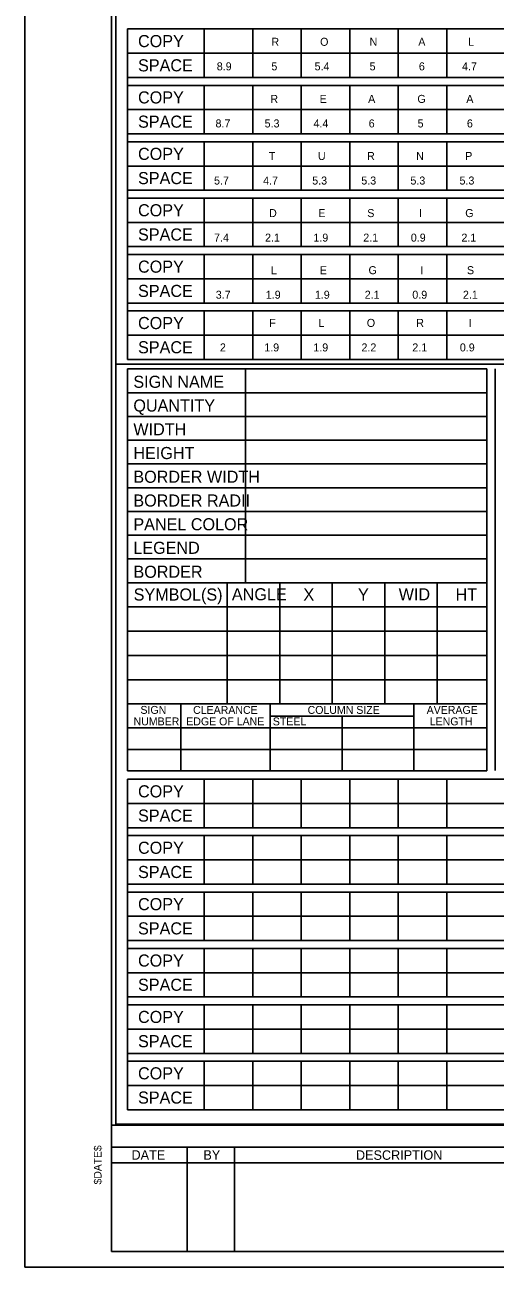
# Model space of a CAD drawing. Extents: x 17890628 to 17890844, y 17897693 to 17898031.
# Drawn here: x 17890700.5 to 17890726.4, y 17897907.6 to 17897976.1 of the extents above; entities that cross this region are included whole.
import ezdxf

# ---------------------------------------------------------------- set-up
doc = ezdxf.new("R2010")
doc.units = 0
for name, color, linetype in [('GSSign', 7, 'Continuous'), ('PlotBorder_dp', 7, 'Continuous'), ('SheetBorder_dp', 7, 'Continuous'), ('SheetLines_dp', 7, 'Continuous'), ('SheetLinesMisc2_dp', 7, 'Continuous'), ('TextMinor', 7, 'Continuous'), ('TextMisc', 7, 'Continuous')]:
    doc.layers.add(name, color=color, linetype=linetype)

msp = doc.modelspace()

# ---------------------------------------------------------------- linework, layer by layer
at = {"layer": 'PlotBorder_dp'}
msp.add_lwpolyline([(17890700.471, 17897907.61), (17890843.989, 17897907.61), (17890843.989, 17897999.809), (17890700.471, 17897999.809)], close=True, dxfattribs=at)
at = {"layer": 'SheetBorder_dp'}
for p, q in [((17890705.254, 17897998.94), (17890705.254, 17897908.479)), ((17890705.254, 17897915.438), (17890839.205, 17897915.438)), ((17890705.254, 17897908.479), (17890839.205, 17897908.479))]:
    msp.add_line(p, q, dxfattribs=at)
at = {"layer": 'SheetLines_dp'}
for p, q in [((17890705.254, 17897914.22), (17890755.355, 17897914.22)), ((17890709.43, 17897914.22), (17890709.43, 17897908.479)), ((17890712.039, 17897914.22), (17890712.039, 17897908.479)), ((17890705.254, 17897913.35), (17890755.355, 17897913.35))]:
    msp.add_line(p, q, dxfattribs=at)
at = {"layer": 'SheetLinesMisc2_dp'}
for p, q in [((17890705.5, 17897998.732), (17890705.5, 17897915.484)), ((17890706.142, 17897975.843), (17890771.912, 17897975.843)), ((17890706.142, 17897957.633), (17890706.142, 17897975.843)), ((17890710.375, 17897975.843), (17890710.375, 17897973.171)), ((17890713.051, 17897975.843), (17890713.051, 17897973.171)), ((17890715.727, 17897975.843), (17890715.727, 17897973.171)), ((17890718.402, 17897975.843), (17890718.402, 17897973.171)), ((17890721.077, 17897975.843), (17890721.077, 17897973.171)), ((17890723.753, 17897975.843), (17890723.753, 17897973.171)), ((17890706.142, 17897974.507), (17890771.912, 17897974.507)), ((17890706.142, 17897973.171), (17890771.912, 17897973.171)), ((17890706.142, 17897972.735), (17890771.912, 17897972.735)), ((17890710.375, 17897972.735), (17890710.375, 17897970.064)), ((17890713.051, 17897972.735), (17890713.051, 17897970.064)), ((17890715.727, 17897972.735), (17890715.727, 17897970.064)), ((17890718.402, 17897972.735), (17890718.402, 17897970.064)), ((17890721.077, 17897972.735), (17890721.077, 17897970.064)), ((17890723.753, 17897972.735), (17890723.753, 17897970.064)), ((17890706.142, 17897971.399), (17890771.912, 17897971.4)), ((17890706.142, 17897970.064), (17890771.912, 17897970.064)), ((17890706.142, 17897969.628), (17890771.912, 17897969.628)), ((17890710.375, 17897969.628), (17890710.375, 17897966.956)), ((17890713.051, 17897969.628), (17890713.051, 17897966.956)), ((17890715.727, 17897969.628), (17890715.727, 17897966.956)), ((17890718.402, 17897969.628), (17890718.402, 17897966.956)), ((17890721.077, 17897969.628), (17890721.077, 17897966.956)), ((17890723.753, 17897969.628), (17890723.753, 17897966.956)), ((17890706.142, 17897968.292), (17890771.912, 17897968.292)), ((17890706.142, 17897966.956), (17890771.912, 17897966.956)), ((17890706.142, 17897966.52), (17890771.912, 17897966.52)), ((17890710.375, 17897966.52), (17890710.375, 17897963.848)), ((17890713.051, 17897966.52), (17890713.051, 17897963.848)), ((17890715.727, 17897966.52), (17890715.727, 17897963.848)), ((17890718.402, 17897966.52), (17890718.402, 17897963.848)), ((17890721.077, 17897966.52), (17890721.077, 17897963.848)), ((17890723.753, 17897966.52), (17890723.753, 17897963.848)), ((17890706.142, 17897965.184), (17890771.912, 17897965.184)), ((17890706.142, 17897963.848), (17890771.912, 17897963.848)), ((17890706.142, 17897963.412), (17890771.912, 17897963.412)), ((17890710.375, 17897963.412), (17890710.375, 17897960.74)), ((17890713.051, 17897963.412), (17890713.051, 17897960.74)), ((17890715.727, 17897963.412), (17890715.727, 17897960.74)), ((17890718.402, 17897963.412), (17890718.402, 17897960.74)), ((17890721.077, 17897963.412), (17890721.077, 17897960.74)), ((17890723.753, 17897963.412), (17890723.753, 17897960.74)), ((17890706.142, 17897962.076), (17890771.912, 17897962.076)), ((17890706.142, 17897960.74), (17890771.912, 17897960.74)), ((17890706.142, 17897960.304), (17890771.912, 17897960.304)), ((17890710.375, 17897960.304), (17890710.375, 17897957.633)), ((17890713.051, 17897960.304), (17890713.051, 17897957.633)), ((17890715.727, 17897960.304), (17890715.727, 17897957.633)), ((17890718.402, 17897960.304), (17890718.402, 17897957.633)), ((17890721.077, 17897960.304), (17890721.077, 17897957.633)), ((17890723.753, 17897960.304), (17890723.753, 17897957.633)), ((17890706.142, 17897958.969), (17890771.912, 17897958.969)), ((17890705.5, 17897957.37), (17890839.233, 17897957.37)), ((17890706.142, 17897957.633), (17890771.912, 17897957.633)), ((17890706.142, 17897934.953), (17890706.142, 17897957.108)), ((17890706.142, 17897957.108), (17890725.973, 17897957.108)), ((17890712.643, 17897957.108), (17890712.643, 17897955.799)), ((17890725.973, 17897957.108), (17890725.973, 17897934.953)), ((17890726.429, 17897957.109), (17890726.429, 17897934.985)), ((17890706.142, 17897955.799), (17890725.973, 17897955.799)), ((17890712.643, 17897955.799), (17890712.643, 17897945.327)), ((17890706.142, 17897954.491), (17890725.973, 17897954.491)), ((17890706.142, 17897953.182), (17890725.973, 17897953.182)), ((17890706.142, 17897951.874), (17890725.973, 17897951.874)), ((17890706.142, 17897950.565), (17890725.973, 17897950.565)), ((17890706.142, 17897949.256), (17890725.973, 17897949.256)), ((17890706.142, 17897947.948), (17890716.057, 17897947.948)), ((17890716.057, 17897947.948), (17890725.973, 17897947.948)), ((17890706.142, 17897946.639), (17890716.057, 17897946.639)), ((17890716.057, 17897946.639), (17890725.973, 17897946.639)), ((17890706.141, 17897945.327), (17890725.973, 17897945.327)), ((17890711.644, 17897945.327), (17890711.644, 17897938.646)), ((17890714.542, 17897945.327), (17890714.542, 17897938.646)), ((17890717.44, 17897945.327), (17890717.44, 17897938.646)), ((17890720.337, 17897945.327), (17890720.337, 17897938.646)), ((17890723.235, 17897945.327), (17890723.235, 17897938.646)), ((17890706.141, 17897943.991), (17890725.973, 17897943.991)), ((17890706.141, 17897942.655), (17890725.973, 17897942.655)), ((17890706.141, 17897941.319), (17890725.973, 17897941.319)), ((17890706.141, 17897939.982), (17890725.973, 17897939.982)), ((17890706.141, 17897938.646), (17890725.973, 17897938.646)), ((17890709.08, 17897938.646), (17890709.08, 17897934.953)), ((17890714.015, 17897938.646), (17890714.015, 17897934.953)), ((17890721.947, 17897938.646), (17890721.947, 17897934.953)), ((17890714.015, 17897937.966), (17890721.947, 17897937.966)), ((17890717.981, 17897937.966), (17890717.981, 17897934.953)), ((17890706.141, 17897937.327), (17890725.973, 17897937.327)), ((17890706.141, 17897936.14), (17890725.973, 17897936.14)), ((17890706.142, 17897934.953), (17890725.973, 17897934.953)), ((17890706.142, 17897934.497), (17890771.912, 17897934.497)), ((17890706.142, 17897916.286), (17890706.142, 17897934.497)), ((17890710.375, 17897934.497), (17890710.375, 17897931.825)), ((17890713.051, 17897934.497), (17890713.051, 17897931.825)), ((17890715.727, 17897934.497), (17890715.727, 17897931.825)), ((17890718.402, 17897934.497), (17890718.402, 17897931.825)), ((17890721.077, 17897934.497), (17890721.077, 17897931.825)), ((17890723.753, 17897934.497), (17890723.753, 17897931.825)), ((17890706.142, 17897933.162), (17890771.912, 17897933.162)), ((17890706.142, 17897931.825), (17890771.912, 17897931.825)), ((17890706.142, 17897931.389), (17890771.912, 17897931.389)), ((17890710.375, 17897931.389), (17890710.375, 17897928.717)), ((17890713.051, 17897931.389), (17890713.051, 17897928.717)), ((17890715.727, 17897931.389), (17890715.727, 17897928.717)), ((17890718.402, 17897931.389), (17890718.402, 17897928.717)), ((17890721.077, 17897931.389), (17890721.077, 17897928.717)), ((17890723.753, 17897931.389), (17890723.753, 17897928.717)), ((17890706.142, 17897930.053), (17890771.912, 17897930.053)), ((17890706.142, 17897928.717), (17890771.912, 17897928.717)), ((17890706.142, 17897928.281), (17890771.912, 17897928.281)), ((17890710.375, 17897928.281), (17890710.375, 17897925.609)), ((17890713.051, 17897928.281), (17890713.051, 17897925.609)), ((17890715.727, 17897928.281), (17890715.727, 17897925.609)), ((17890718.402, 17897928.281), (17890718.402, 17897925.609)), ((17890721.077, 17897928.281), (17890721.077, 17897925.609)), ((17890723.753, 17897928.281), (17890723.753, 17897925.609)), ((17890706.142, 17897926.945), (17890771.912, 17897926.945)), ((17890706.142, 17897925.609), (17890771.912, 17897925.609)), ((17890706.142, 17897925.173), (17890771.912, 17897925.173)), ((17890710.375, 17897925.173), (17890710.375, 17897922.501)), ((17890713.051, 17897925.173), (17890713.051, 17897922.501)), ((17890715.727, 17897925.173), (17890715.727, 17897922.501)), ((17890718.402, 17897925.173), (17890718.402, 17897922.501)), ((17890721.077, 17897925.173), (17890721.077, 17897922.501)), ((17890723.753, 17897925.173), (17890723.753, 17897922.501)), ((17890706.142, 17897923.838), (17890771.912, 17897923.838)), ((17890706.142, 17897922.501), (17890771.912, 17897922.501)), ((17890706.142, 17897922.065), (17890771.912, 17897922.065)), ((17890710.375, 17897922.065), (17890710.375, 17897919.393)), ((17890713.051, 17897922.065), (17890713.051, 17897919.393)), ((17890715.727, 17897922.065), (17890715.727, 17897919.393)), ((17890718.402, 17897922.065), (17890718.402, 17897919.393)), ((17890721.077, 17897922.065), (17890721.077, 17897919.393)), ((17890723.753, 17897922.065), (17890723.753, 17897919.393)), ((17890706.142, 17897920.729), (17890771.912, 17897920.729)), ((17890706.142, 17897919.393), (17890771.912, 17897919.393)), ((17890706.142, 17897918.958), (17890771.912, 17897918.958)), ((17890710.375, 17897918.958), (17890710.375, 17897916.286)), ((17890713.051, 17897918.958), (17890713.051, 17897916.286)), ((17890715.727, 17897918.958), (17890715.727, 17897916.286)), ((17890718.402, 17897918.958), (17890718.402, 17897916.286)), ((17890721.077, 17897918.958), (17890721.077, 17897916.286)), ((17890723.753, 17897918.958), (17890723.753, 17897916.286)), ((17890706.142, 17897917.622), (17890771.912, 17897917.622)), ((17890706.142, 17897916.286), (17890771.912, 17897916.286)), ((17890705.5, 17897915.484), (17890839.233, 17897915.484))]:
    msp.add_line(p, q, dxfattribs=at)

# ---------------------------------------------------------------- texts
at = {"layer": 'GSSign'}
for s, height, p in [('R', 0.441, (17890714.078, 17897974.917)), ('O', 0.441, (17890716.767, 17897974.917)), ('N', 0.441, (17890719.497, 17897974.917)), ('A', 0.441, (17890722.185, 17897974.917)), ('L', 0.441, (17890724.937, 17897974.917)), ('8.9', 0.4411, (17890711.064, 17897973.564)), ('5', 0.441, (17890714.078, 17897973.564)), ('5.4', 0.4411, (17890716.462, 17897973.564)), ('5', 0.441, (17890719.497, 17897973.564)), ('6', 0.441, (17890722.217, 17897973.564)), ('4.7', 0.4411, (17890724.6, 17897973.564)), ('R', 0.441, (17890714.02, 17897971.77)), ('E', 0.441, (17890716.74, 17897971.77)), ('A', 0.441, (17890719.417, 17897971.77)), ('G', 0.441, (17890722.137, 17897971.77)), ('A', 0.441, (17890724.836, 17897971.77)), ('8.7', 0.4411, (17890710.995, 17897970.418)), ('5.3', 0.4411, (17890713.705, 17897970.418)), ('4.4', 0.4411, (17890716.404, 17897970.418)), ('6', 0.441, (17890719.449, 17897970.418)), ('5', 0.441, (17890722.148, 17897970.418)), ('6', 0.441, (17890724.868, 17897970.418)), ('T', 0.441, (17890713.938, 17897968.624)), ('U', 0.441, (17890716.647, 17897968.624)), ('R', 0.441, (17890719.357, 17897968.624)), ('N', 0.441, (17890722.066, 17897968.624)), ('P', 0.441, (17890724.775, 17897968.624)), ('5.7', 0.4411, (17890710.914, 17897967.271)), ('4.7', 0.4411, (17890713.623, 17897967.271)), ('5.3', 0.4411, (17890716.332, 17897967.271)), ('5.3', 0.4411, (17890719.041, 17897967.271)), ('5.3', 0.4411, (17890721.751, 17897967.271)), ('5.3', 0.4411, (17890724.46, 17897967.271)), ('D', 0.441, (17890713.95, 17897965.477)), ('E', 0.441, (17890716.669, 17897965.477)), ('S', 0.441, (17890719.368, 17897965.477)), ('I', 0.441, (17890722.225, 17897965.477)), ('G', 0.441, (17890724.776, 17897965.477)), ('7.4', 0.4411, (17890710.915, 17897964.125)), ('2.1', 0.4411, (17890713.729, 17897964.125)), ('1.9', 0.4411, (17890716.396, 17897964.125)), ('2.1', 0.4411, (17890719.148, 17897964.125)), ('0.9', 0.4411, (17890721.773, 17897964.125)), ('2.1', 0.4411, (17890724.566, 17897964.125)), ('L', 0.441, (17890714.053, 17897962.33)), ('E', 0.441, (17890716.751, 17897962.33)), ('G', 0.441, (17890719.44, 17897962.33)), ('I', 0.441, (17890722.307, 17897962.33)), ('S', 0.441, (17890724.869, 17897962.33)), ('3.7', 0.4411, (17890711.007, 17897960.978)), ('1.9', 0.4411, (17890713.769, 17897960.978)), ('1.9', 0.4411, (17890716.478, 17897960.978)), ('2.1', 0.4411, (17890719.23, 17897960.978)), ('0.9', 0.4411, (17890721.855, 17897960.978)), ('2.1', 0.4411, (17890724.648, 17897960.978)), ('F', 0.441, (17890713.957, 17897959.426)), ('L', 0.441, (17890716.677, 17897959.426)), ('O', 0.441, (17890719.344, 17897959.426)), ('R', 0.441, (17890722.074, 17897959.426)), ('I', 0.441, (17890724.96, 17897959.426)), ('2', 0.441, (17890711.237, 17897958.074)), ('1.9', 0.4411, (17890713.684, 17897958.074)), ('1.9', 0.4411, (17890716.393, 17897958.074)), ('2.2', 0.4411, (17890719.05, 17897958.074)), ('2.1', 0.4411, (17890721.854, 17897958.074)), ('0.9', 0.4411, (17890724.479, 17897958.074))]:
    msp.add_text(s, height=height, dxfattribs=at).set_placement(p)
at = {"layer": 'TextMinor'}
for s, height, p in [('COPY', 0.6667, (17890706.719, 17897974.843)), ('SPACE', 0.6667, (17890706.719, 17897973.507)), ('COPY', 0.6667, (17890706.719, 17897971.739)), ('SPACE', 0.6667, (17890706.719, 17897970.403)), ('COPY', 0.6667, (17890706.719, 17897968.628)), ('SPACE', 0.6667, (17890706.719, 17897967.292)), ('COPY', 0.6667, (17890706.719, 17897965.521)), ('SPACE', 0.6667, (17890706.719, 17897964.185)), ('COPY', 0.6667, (17890706.719, 17897962.413)), ('SPACE', 0.6667, (17890706.719, 17897961.076)), ('COPY', 0.6667, (17890706.719, 17897959.306)), ('SPACE', 0.6667, (17890706.719, 17897957.97)), ('SIGN NAME', 0.6667, (17890706.461, 17897956.068)), ('QUANTITY', 0.6667, (17890706.461, 17897954.76)), ('WIDTH', 0.6667, (17890706.461, 17897953.451)), ('HEIGHT', 0.6667, (17890706.461, 17897952.142)), ('BORDER WIDTH', 0.66667, (17890706.461, 17897950.834)), ('BORDER RADII', 0.66667, (17890706.461, 17897949.525)), ('PANEL COLOR', 0.66667, (17890706.461, 17897948.216)), ('LEGEND', 0.6667, (17890706.461, 17897946.919)), ('BORDER', 0.6667, (17890706.467, 17897945.599)), ('SYMBOL(S)', 0.6667, (17890706.478, 17897944.345)), ('ANGLE', 0.6667, (17890711.899, 17897944.358)), ('X', 0.667, (17890715.846, 17897944.345)), ('Y', 0.667, (17890718.859, 17897944.345)), ('WID', 0.6667, (17890721.103, 17897944.358)), ('HT', 0.6667, (17890724.244, 17897944.346)), ('SIGN', 0.4357, (17890706.852, 17897938.102)), ('CLEARANCE', 0.4357, (17890709.759, 17897938.1)), ('COLUMN SIZE', 0.43573, (17890716.077, 17897938.1)), ('AVERAGE', 0.4357, (17890722.648, 17897938.1)), ('NUMBER', 0.4357, (17890706.473, 17897937.468)), ('EDGE OF LANE', 0.43573, (17890709.38, 17897937.468)), ('STEEL    ', 0.4357, (17890714.156, 17897937.468)), ('LENGTH', 0.4357, (17890722.817, 17897937.468)), ('COPY', 0.6667, (17890706.719, 17897933.498)), ('SPACE', 0.6667, (17890706.719, 17897932.162)), ('COPY', 0.6667, (17890706.719, 17897930.389)), ('SPACE', 0.6667, (17890706.719, 17897929.053)), ('COPY', 0.6667, (17890706.719, 17897927.282)), ('SPACE', 0.6667, (17890706.719, 17897925.946)), ('COPY', 0.6667, (17890706.719, 17897924.173)), ('SPACE', 0.6667, (17890706.719, 17897922.838)), ('COPY', 0.6667, (17890706.719, 17897921.065)), ('SPACE', 0.6667, (17890706.719, 17897919.729)), ('COPY', 0.6667, (17890706.719, 17897917.958)), ('SPACE', 0.6667, (17890706.719, 17897916.622))]:
    msp.add_text(s, height=height, dxfattribs=at).set_placement(p)
msp.add_text('$DATE$', height=0.4262, rotation=90, dxfattribs=at).set_placement((17890704.706, 17897912.169))
at = {"layer": 'TextMisc'}
for s, height, rotation, p in [('DATE', 0.5219, 359.86925, (17890706.359, 17897913.533)), ('DESCRIPTION', 0.52178, 0.04975, (17890718.745, 17897913.524))]:
    msp.add_text(s, height=height, rotation=rotation, dxfattribs=at).set_placement(p)
msp.add_text('BY', height=0.5219, dxfattribs=at).set_placement((17890710.325, 17897913.533))

doc.saveas('drawing.dxf')
